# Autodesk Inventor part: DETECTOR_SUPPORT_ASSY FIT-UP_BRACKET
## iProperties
Shininess: 64.0
Length Units: 11272
Angle Units: 11279
Time Units: 11290
Mass Units: 11286
Length Display Precision: 3
Angle Display Precision: 2
Compacted: True
Part Number: DETECTOR_SUPPORT_ASSY FIT-UP_BRACKET
Document SubType Name: Modeling
Created: 2004-08
Designer: John Blackburn
Material: ALUMINUM
Manufacturer: Standard
Standards Organization: Custom
Density: 0.0
Volumn: 0.0
Area: 0.0
PropertySet Name: Model Information
Control State: 0
Master: False
Checked Out: False
Author: John Blackburn
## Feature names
1. ExtrusionMidplane1
2. AM_HOLE_SI0030_1 [Hole]
3. Rectangular Pattern1
